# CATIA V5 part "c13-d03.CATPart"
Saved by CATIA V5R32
Part number: Part1
Bounding box of the stored display mesh (mm): x 0 to 136, y 0 to 120, z 0 to 120
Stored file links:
  D:\PROJECTS\Project 2022\CATIA V5 6R 2022\Resources\Part Files\c13_catia_v5_6r2022_prt\c13_catia_v5-6r2022_figr_13-15 & 16\c13-d03.CATPart
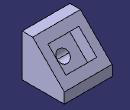
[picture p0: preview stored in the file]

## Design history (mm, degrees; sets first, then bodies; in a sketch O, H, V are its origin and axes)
Body1 (main body)
  Sketch1 on yz-plane, origin (0, 0, 0), H (0, 1, 0), V (0, 0, 1)
    line L1 (0, 0) -> (0, 120)
    line L2 (0, 120) -> (30, 120)
    line L3 (30, 120) -> (120, 30)
    line L4 (120, 30) -> (120, 0)
    point P4 (120, 0)
    line L5 (120, 0) -> (0, 0)
    length L1 = 120
    length L5 = 120
    length L4 = 30
    length L2 = 30
    vertical: L1 V, L4 V
    horizontal: L2 H, L5 H
    coincidence: P4 H
  Pad1: profile Sketch1, direction (1, 0, 0), length 136
  Sketch2 on face of Pad1, origin (0, 75, 75), H (-1, 0, 0), V (0, -0.7071, 0.7071)
    line L1 (-111.9577, 36.0679) -> (-24.0423, 36.0679)
    line L2 (-24.0423, 36.0679) -> (-24.0423, -36.0679)
    line L3 (-24.0423, -36.0679) -> (-111.9577, -36.0679)
    line L4 (-111.9577, -36.0679) -> (-111.9577, 36.0679)
    construction line L5 (-136, 63.6396) -> (0, -63.6396)
    point P5 (-136, 63.6396)
    point P6 (0, -63.6396)
    reference projected point E1 (0, -63.6396) from vertex [face of Pad1 | face of Pad1 | face of Pad1]
    reference projected point E2 (-136, 63.6396) from vertex [face of Pad1 | face of Pad1 | face of Pad1]
    axis line L6 (-111.9577, -36.0679) -> (-24.0423, 36.0679)
    point P7 (-68, 0)
    horizontal: L1 H, L3 H
    vertical: L2 V, L4 V
    coincidence: E1 P6, P5 E2
    midpoint: P7 L5, P7 L6
  Pocket1: profile Sketch2, direction (0, -0.7071, -0.7071), length 37
  Sketch3 on face of Pocket1, origin (0, 48.837, 48.837), H (-1, 0, 0), V (0, -0.7071, 0.7071)
    axis line L1 (-24.0423, -36.0679) -> (-111.9577, 36.0679)
    point P1 (-24.0423, -36.0679)
    point P2 (-111.9577, 36.0679)
    reference projected point E1 (-24.0423, -36.0679) from vertex [face of Pocket1 | face of Pad1 | face of Pocket1]
    reference projected point E2 (-111.9577, 36.0679) from vertex [face of Pocket1 | face of Pad1 | face of Pocket1]
    circle A1 centre (-68, 0) radius 17.073
    point P3 (-68, 0)
    point P4 (-50.927, 0)
    coincidence: P1 E1, P2 E2, A1 P4, P4 H
    midpoint: P3 L1
  Pocket2: profile Sketch3, direction (0, -0.7071, -0.7071), through (limit type 3)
